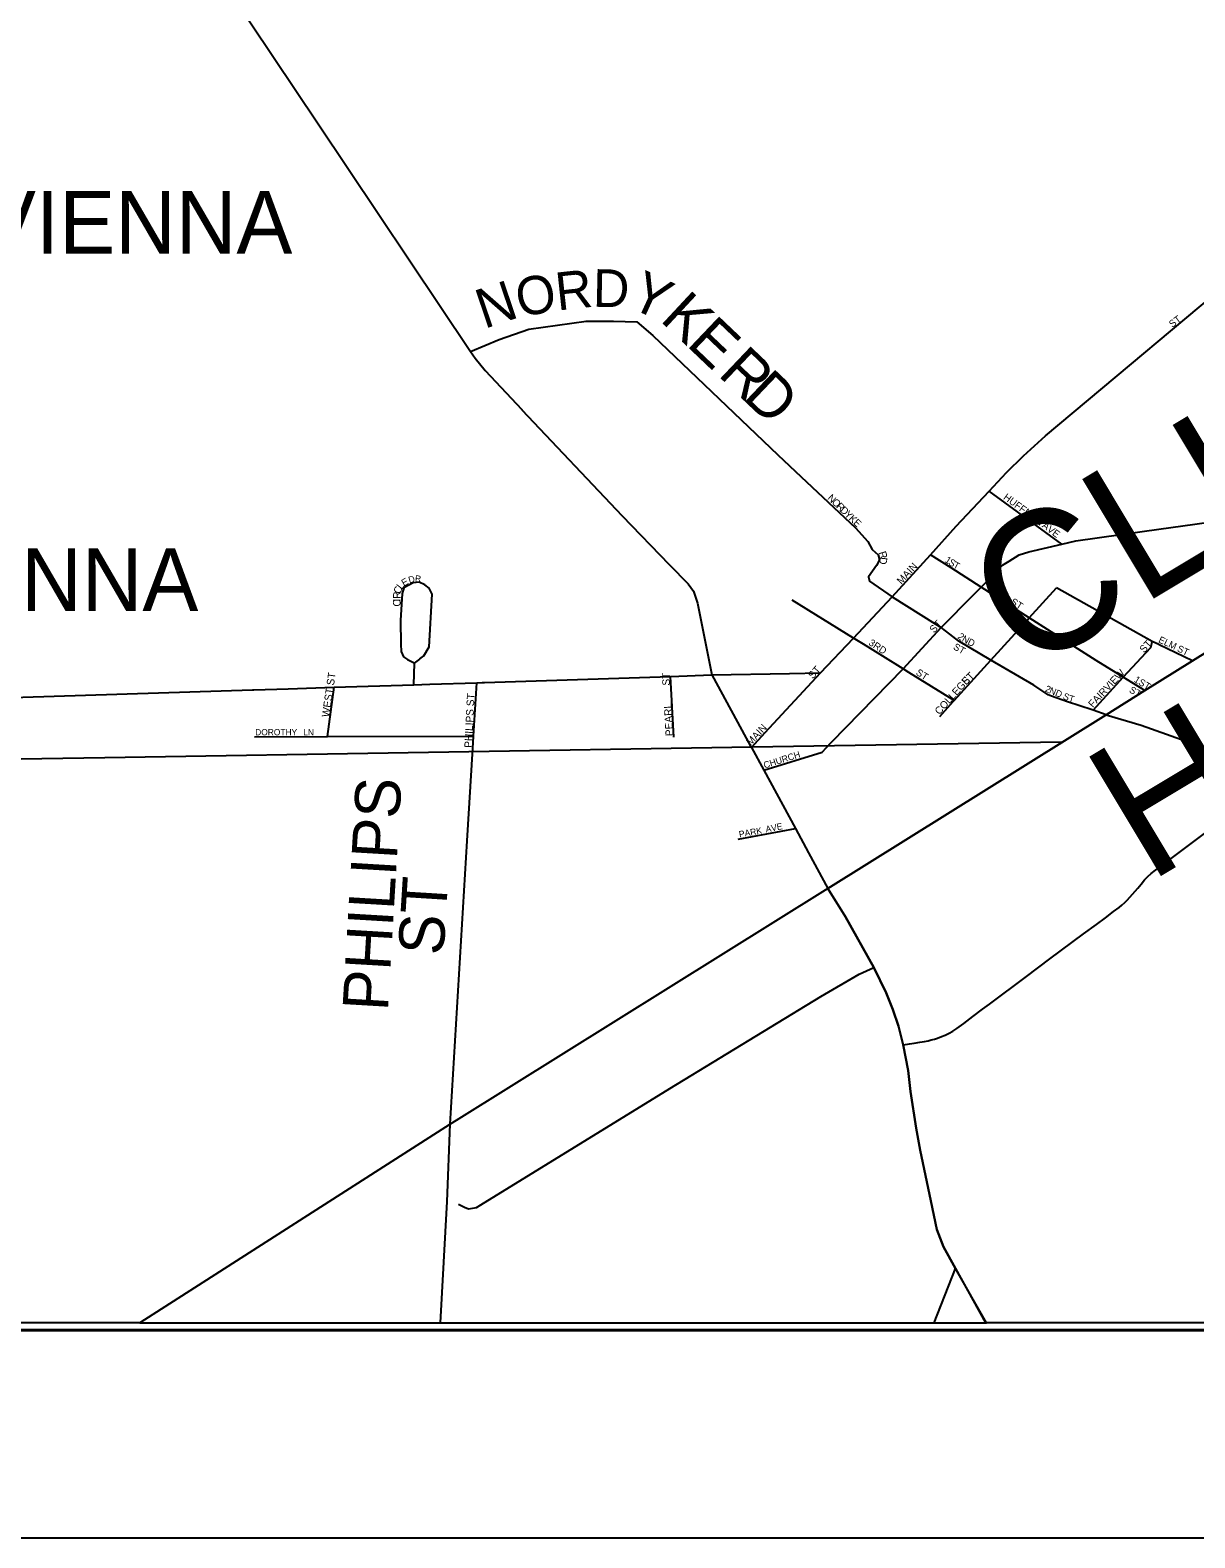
# Model space of a CAD drawing. Extents: x 0 to 784, y 0 to 440.
# Drawn here: x 82.4 to 138.7, y 0 to 72.8 of the extents above; entities that cross this region are included whole.
import ezdxf

# ---------------------------------------------------------------- set-up
doc = ezdxf.new("R2010")
doc.units = 0
for name, color, linetype in [('Default', 7, 'Continuous'), ('SH_Border', 7, 'Continuous'), ('SH_Cut_Line', 7, 'Continuous')]:
    doc.layers.add(name, color=color, linetype=linetype)

msp = doc.modelspace()

# ---------------------------------------------------------------- linework, layer by layer
at = {"layer": 'Default'}
for p, q in [((87.731, 10.383), (30.041, 10.383)), ((87.731, 10.383), (128.622, 10.383)), ((392.022, 10.383), (128.622, 10.383))]:
    msp.add_line(p, q, dxfattribs=at)
msp.add_lwpolyline([(31.327, 429.991), (465.774, 429.991), (465.774, 10.05), (31.327, 10.05)], close=True, dxfattribs=at)
for points in [[(63.035, 101.124), (63.172, 100.901), (63.704, 100.327), (64.468, 99.673), (66.9, 97.949), (69.807, 96.03), (70.356, 95.679), (73.131, 93.903), (78.147, 90.573), (81.809, 88.158), (83.046, 87.271), (83.611, 86.769), (83.991, 86.405), (84.356, 86.03), (85.588, 84.33), (96.319, 68.321), (103.702, 57.281), (103.922, 56.947), (104.41, 56.35), (106.182, 54.472), (106.189, 54.465)], [(219.536, 92.843), (188.738, 73.633), (169.463, 61.61), (151.924, 50.668), (138.566, 42.336), (136.273, 40.905), (134.391, 39.732), (120.964, 31.355), (103.003, 20.149), (102.719, 19.968), (87.731, 10.383)], [(212.87, 88.686), (188.738, 73.633), (169.463, 61.61), (151.924, 50.668), (138.566, 42.336), (136.273, 40.905), (134.391, 39.732), (120.964, 31.355), (103.003, 20.149), (102.719, 19.968), (87.731, 10.383)], [(212.87, 88.686), (188.738, 73.633), (169.463, 61.61), (151.924, 50.668), (138.566, 42.336), (136.273, 40.905), (134.391, 39.732), (120.964, 31.355), (103.003, 20.149), (102.719, 19.968), (87.731, 10.383)], [(212.87, 88.686), (188.738, 73.633), (169.463, 61.61), (151.924, 50.668), (138.566, 42.336), (136.273, 40.905), (134.391, 39.732), (120.964, 31.355), (103.003, 20.149), (102.719, 19.968), (87.731, 10.383)], [(124.064, 45.424), (125.912, 47.462), (127.157, 48.835), (128.748, 50.533), (129.588, 51.429), (130.412, 52.245), (131.474, 53.2), (141.654, 61.732), (142.269, 62.241)], [(128.622, 10.383), (127.13, 12.999), (126.55, 14.052), (126.217, 14.894), (125.93, 16.269), (125.416, 18.712), (125.219, 19.777), (124.947, 21.545), (124.83, 22.567), (124.598, 23.795), (124.363, 24.709), (124.1, 25.512), (123.777, 26.306), (123.179, 27.538), (121.803, 29.982), (120.964, 31.355), (134.391, 39.732), (136.273, 40.905), (138.566, 42.336), (151.924, 50.668), (169.463, 61.61), (184.827, 56.049)], [(103.702, 57.281), (105.095, 57.855), (106.513, 58.354), (109.287, 58.734), (110.604, 58.734), (111.742, 58.701), (112.5, 58.04), (118.547, 52.287), (119.668, 51.232)], [(106.189, 54.465), (111.027, 49.341), (113.303, 46.992), (113.312, 46.983)], [(119.668, 51.232), (122.289, 48.765), (122.887, 48.096), (123.1, 47.718), (123.382, 47.455), (123.446, 47.21), (123.304, 46.947), (122.916, 46.399), (122.967, 46.191), (124.064, 45.424)], [(132.25, 47.973), (128.748, 50.533)], [(136.245, 48.596), (139.376, 49.038)], [(126.137, 44.13), (126.434, 43.945), (128.011, 45.539), (128.361, 45.899), (129.391, 46.956), (129.707, 47.153), (130.203, 47.454), (130.664, 47.611), (132.25, 47.973), (132.926, 48.128), (136.245, 48.596)], [(133.908, 42.359), (130.685, 44.416), (128.361, 45.899), (126.913, 46.823), (125.912, 47.462)], [(113.312, 46.983), (114.214, 46.053), (114.477, 45.705), (114.658, 45.129), (115.36, 41.658)], [(101.251, 42.423), (101.259, 42.43), (101.457, 42.59), (101.706, 43.01), (101.848, 45.558), (101.711, 45.841), (101.496, 46.004), (101.222, 46.132), (100.928, 46.102), (100.719, 45.998), (100.479, 45.858), (100.397, 45.592), (100.324, 44.281), (100.331, 43.139), (100.349, 42.786), (100.472, 42.54), (100.659, 42.402), (100.976, 42.249)], [(130.483, 44.194), (130.685, 44.416), (132.002, 45.866)], [(136.958, 43.117), (136.948, 43.122), (136.624, 43.279), (132.002, 45.866)], [(122.682, 43.142), (122.197, 43.443), (119.24, 45.275)], [(120.61, 41.759), (122.197, 43.443), (124.064, 45.424)], [(124.064, 45.424), (126.137, 44.13)], [(121.123, 38.392), (121.155, 38.425), (124.591, 41.959), (126.434, 43.945)], [(131.591, 40.705), (130.898, 41.161), (128.834, 42.377), (127.28, 43.292), (126.844, 43.622), (126.434, 43.945)], [(127.011, 40.37), (127.063, 40.427), (128.834, 42.377), (130.483, 44.194), (130.483, 44.194)], [(123.621, 42.56), (122.682, 43.142), (122.682, 43.142)], [(133.768, 39.965), (135.226, 41.547), (136.554, 42.99), (136.605, 43.171), (136.624, 43.279)], [(138.566, 42.336), (136.958, 43.117)], [(100.968, 41.184), (101.005, 42.224), (101.251, 42.423)], [(124.873, 41.785), (124.591, 41.959), (123.621, 42.56), (123.621, 42.56)], [(135.09, 41.631), (133.908, 42.359)], [(104.38, 41.295), (113.363, 41.592), (115.36, 41.658), (119.11, 41.73), (119.11, 41.73)], [(113.519, 38.651), (113.363, 41.592)], [(115.36, 41.658), (117.228, 38.224)], [(117.935, 38.874), (120.61, 41.759)], [(119.11, 41.73), (120.61, 41.759)], [(127.063, 40.427), (124.873, 41.785)], [(136.273, 40.905), (135.226, 41.547), (135.09, 41.631)], [(30.041, 39.131), (33.891, 39.192), (45.613, 39.503), (51.783, 39.675), (56.236, 39.799), (80.551, 40.542), (93.18, 40.941), (93.237, 40.943)], [(93.237, 40.943), (94.902, 40.995), (97.12, 41.064), (100.968, 41.184), (101.741, 41.208), (104.002, 41.283), (104.265, 41.291), (104.38, 41.295)], [(96.793, 38.688), (97.12, 41.064)], [(103.81, 38.101), (103.847, 38.708), (104.002, 41.283)], [(126.36, 39.653), (127.011, 40.37), (127.011, 40.37)], [(134.391, 39.732), (133.768, 39.965), (133.726, 39.981), (132.525, 40.354), (131.759, 40.63), (131.591, 40.705)], [(134.391, 39.732), (136.095, 39.238), (138.765, 38.286), (140.958, 37.507), (142.258, 36.987), (143.241, 36.592), (143.643, 36.382), (144.374, 35.912), (146.552, 34.367), (151.058, 31.041), (162.123, 22.467), (171.478, 15.253), (171.854, 15.075), (172.187, 14.946), (172.478, 14.891), (172.83, 14.908), (173.432, 14.919), (173.975, 14.968), (174.428, 14.897), (174.934, 14.692), (175.251, 14.515), (175.512, 13.987), (176.561, 10.383)], [(93.278, 38.679), (96.793, 38.688), (103.847, 38.708)], [(117.267, 38.153), (117.934, 38.873), (117.935, 38.874)], [(30.041, 36.801), (33.313, 36.839), (51.638, 37.13), (86.049, 37.667), (117.307, 38.184), (132.228, 38.437)], [(103.542, 33.647), (103.542, 33.648), (103.81, 38.101), (103.81, 38.101)], [(117.228, 38.224), (117.267, 38.153), (117.86, 37.061), (119.389, 34.25), (120.03, 33.072), (120.03, 33.072)], [(117.86, 37.061), (120.685, 37.938), (121.11, 38.379), (121.123, 38.392)], [(116.631, 33.725), (119.389, 34.25)], [(124.598, 23.795), (124.909, 23.85), (125.133, 23.887), (125.403, 23.927), (125.618, 23.966), (125.81, 24.003), (125.955, 24.042), (126.107, 24.079), (126.251, 24.126), (126.453, 24.205), (126.616, 24.274), (126.811, 24.366), (126.986, 24.463), (127.195, 24.596), (127.518, 24.838), (127.956, 25.166), (128.431, 25.516), (128.759, 25.769), (130.555, 27.108), (131.682, 27.949), (133.31, 29.157), (133.938, 29.619), (134.361, 29.941), (134.757, 30.233), (135.025, 30.438), (135.151, 30.547), (135.3, 30.67), (135.412, 30.794), (135.672, 31.077), (135.921, 31.365), (136.088, 31.566), (136.256, 31.761), (136.411, 31.921), (136.573, 32.075), (136.778, 32.235), (136.908, 32.338), (137.411, 32.708), (137.927, 33.089), (139.467, 34.248)], [(102.719, 19.968), (103.542, 33.647)], [(120.03, 33.072), (120.964, 31.355)], [(128.622, 10.383), (127.13, 12.999), (126.55, 14.052), (126.217, 14.894), (125.93, 16.269), (125.416, 18.712), (125.219, 19.777), (124.947, 21.545), (124.83, 22.567), (124.598, 23.795), (124.363, 24.709), (124.1, 25.512), (123.777, 26.306), (123.179, 27.538), (121.803, 29.982), (120.964, 31.355), (103.003, 20.149), (102.719, 19.968), (87.731, 10.383)], [(120.964, 31.355), (121.803, 29.982), (123.179, 27.538), (123.777, 26.306), (124.1, 25.512), (124.363, 24.709), (124.598, 23.795), (124.83, 22.567), (124.947, 21.545), (125.219, 19.777), (125.416, 18.712), (125.93, 16.269), (126.217, 14.894), (126.55, 14.052), (127.13, 12.999), (128.567, 10.383)], [(103.119, 16.109), (103.408, 15.969), (103.611, 15.892), (103.993, 15.944), (104.203, 16.085), (113.336, 21.691), (120.616, 26.128), (122.469, 27.217), (123.179, 27.538)], [(102.248, 10.383), (102.581, 16.233), (102.719, 19.968)], [(126.098, 10.383), (127.13, 12.999)], [(87.731, 10.383), (30.041, 10.383)], [(87.731, 10.383), (30.041, 10.383)], [(87.731, 10.383), (30.041, 10.383)]]:
    msp.add_lwpolyline(points, dxfattribs=at)
at = {"layer": 'SH_Border'}
msp.add_lwpolyline([(30, 430), (670, 430), (670, 10), (30, 10)], close=True, dxfattribs=at)
at = {"layer": 'SH_Cut_Line'}
msp.add_lwpolyline([(0, 0), (680, 0), (680, 440), (0, 440)], close=True, dxfattribs=at)

# ---------------------------------------------------------------- texts
at = {"layer": 'Default'}
for s, height, rotation, p in [('CLINTON COUNTY', 6.72139, 30.94604, (130.501, 41.63)), ('HIGHLAND COUNTY', 6.72139, 30.94604, (136.411, 31.572)), ('NEW VIENNA', 3.0305, 0.00001, (69.434, 61.996)), ('R', 1.829, 6.14516, (107.903, 59.249)), ('D', 1.819, 358.78055, (109.601, 59.437)), ('Y', 1.96, 335.38191, (111.266, 59.456)), ('N', 1.908, 18.65516, (104.366, 58.355)), ('O', 1.845, 9.63667, (106.053, 58.933)), ('K', 2.108, 317.06578, (112.804, 58.782)), ('E', 2.112, 316.42388, (114.084, 57.591)), ('ST', 0.3446, 37.20516, (137.59, 58.411)), ('R', 2.112, 316.41507, (115.605, 56.143)), ('D', 2.112, 316.4113, (116.789, 55.017)), ('N', 0.352, 316.18404, (120.91, 50.166)), ('HUFFMAN', 0.3433, 323.8345, (129.402, 50.171)), ('O', 0.352, 316.16962, (121.12, 49.964)), ('R', 0.352, 316.17584, (121.331, 49.762)), ('D', 0.352, 316.16962, (121.52, 49.581)), ('Y', 0.352, 316.17174, (121.731, 49.379)), ('K', 0.352, 316.18781, (121.941, 49.177)), ('E', 0.352, 316.45219, (122.153, 48.974)), ('AVE', 0.3442, 323.14538, (131.27, 48.811)), ('NEW VIENNA', 3.0305, 0.00001, (64.893, 44.748)), ('R', 0.366, 287.60822, (123.399, 47.566)), ('D', 0.366, 264.48525, (123.47, 47.361)), ('1', 0.34, 326.09679, (126.569, 47.131)), ('MAIN', 0.3554, 47.21807, (124.513, 46.004)), ('S', 0.34, 326.12704, (126.744, 47.014)), ('T', 0.332, 331.56024, (126.977, 46.86)), ('C', 0.366, 75.27085, (100.331, 45.554)), ('L', 0.36, 53.77847, (100.381, 45.764)), ('E', 0.336, 30.62344, (100.488, 45.923)), ('D', 0.315, 16.42642, (100.755, 46.08)), ('R', 0.303, 357.28106, (101.02, 46.165)), ('C', 0.366, 89.12052, (100.324, 44.957)), ('I', 0.366, 89.10323, (100.327, 45.197)), ('R', 0.366, 89.10387, (100.329, 45.33)), ('ST', 0.3383, 327.48003, (129.753, 45.107)), ('ST', 0.356, 47.85098, (126.089, 43.656)), ('2', 0.342, 324.74791, (127.19, 43.444)), ('3RD', 0.3397, 326.46802, (122.898, 43.133)), ('ST', 0.3344, 330.16825, (126.981, 42.923)), ('N', 0.333, 331.26189, (127.4, 43.299)), ('D', 0.332, 331.71437, (127.671, 43.15)), ('ST', 0.356, 47.84191, (136.23, 42.696)), ('ELM', 0.3271, 335.11027, (136.892, 43.244)), ('ST', 0.3277, 334.66892, (137.794, 42.817)), ('WEST ST', 0.3658, 81.56785, (96.88, 39.604)), ('ST', 0.3658, 90, (113.329, 41.144)), ('ST', 0.3554, 47.11735, (120.231, 41.443)), ('ST', 0.3383, 327.49755, (125.182, 41.693)), ('COLLEGE', 0.3561, 48.0318, (126.347, 39.71)), ('ST', 0.3533, 44.83855, (127.637, 41.152)), ('FAIRVIEW', 0.3551, 46.80715, (133.752, 40.057)), ('1ST', 0.3367, 328.60036, (135.707, 41.347)), ('PHILIPS ST', 0.3658, 87.08456, (103.768, 38.133)), ('2', 0.324, 337.30211, (131.418, 40.871)), ('N', 0.324, 337.33472, (131.619, 40.787)), ('D', 0.324, 337.3095, (131.907, 40.667)), ('S', 0.324, 337.30519, (132.281, 40.511)), ('ST', 0.3344, 330.16825, (135.479, 40.842)), ('PEARL', 0.3658, 93.13864, (113.49, 38.715)), ('T', 0.314, 344.43329, (132.563, 40.396)), ('DOROTHY', 0.3031, 0.00001, (93.306, 38.744)), ('LN', 0.3031, 0.00001, (95.624, 38.744)), ('MAIN', 0.3552, 46.93773, (117.237, 38.216)), ('CHURCH', 0.3165, 17.55269, (117.909, 37.14)), ('PHILIPS', 2.1949, 86.61297, (99.712, 25.401)), ('PARK', 0.3082, 10.4296, (116.695, 33.809)), ('AVE', 0.3094, 11.70109, (117.981, 34.049)), ('ST', 2.1949, 86.43882, (102.395, 28.093))]:
    msp.add_text(s, height=height, rotation=rotation, dxfattribs=at).set_placement(p)

doc.saveas('drawing.dxf')
